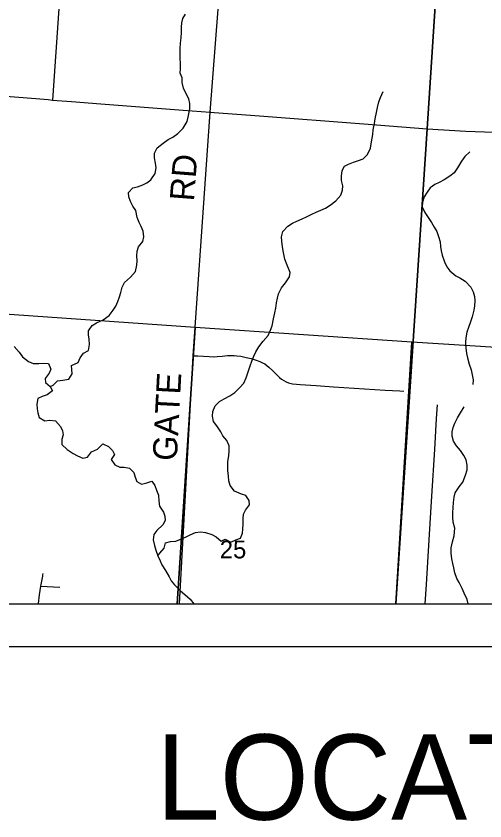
# Model space of a CAD drawing. Extents: x 0 to 34, y 0 to 22.
# Drawn here: x 4.098 to 5.197, y 13.591 to 15.479 of the extents above; entities that cross this region are included whole.
import ezdxf

# ---------------------------------------------------------------- set-up
doc = ezdxf.new("R2010")
doc.units = 0
for name, color, linetype in [('GM_X_Corporation', 7, 'Continuous'), ('GM_X_Minor_River', 7, 'Continuous'), ('GM_X_Section_Text', 7, 'Continuous'), ('GM_X_State_Route', 7, 'Continuous'), ('GM_X_Township_Road', 7, 'Continuous'), ('GM_X_Township_Road_Text', 7, 'Continuous'), ('GM_X_Unincorporated_Text', 7, 'Continuous'), ('SH_Cut_Line', 7, 'Continuous'), ('SH_Data', 7, 'Continuous'), ('SH_Text', 7, 'Continuous')]:
    doc.layers.add(name, color=color, linetype=linetype)

msp = doc.modelspace()

# ---------------------------------------------------------------- linework, layer by layer
at = {"layer": 'GM_X_Corporation'}
for points in [[(2.1, 15.9442), (2.1, 14.1), (4.9875, 14.1), (5.0611, 15.2147), (5.0952, 15.7318), (4.92, 15.7429), (4.5905, 15.7634), (4.2803, 15.787), (3.9945, 15.8088), (3.3132, 15.8609), (2.8362, 15.8952), (2.7799, 15.8989), (2.6921, 15.9056), (2.5827, 15.9132), (2.2903, 15.9292)], [(4.9875, 14.1), (8.9, 14.1), (8.9, 15.4827), (8.6741, 15.4976), (7.6503, 15.5653), (6.838, 15.6206), (6.624, 15.6351), (6.4, 15.6498), (6.1109, 15.6683), (5.9419, 15.6782), (5.0952, 15.7318), (5.0611, 15.2147)]]:
    msp.add_lwpolyline(points, close=True, dxfattribs=at)
at = {"layer": 'GM_X_Minor_River'}
for points in [[(4.1779, 14.6097), (4.1851, 14.6134), (4.1951, 14.6235), (4.2076, 14.6245), (4.2216, 14.6274), (4.229, 14.6399), (4.2287, 14.6501), (4.2277, 14.6596), (4.2433, 14.6663), (4.2483, 14.6773), (4.256, 14.6882), (4.2678, 14.6941), (4.2703, 14.7089), (4.2692, 14.7207), (4.2675, 14.731), (4.2676, 14.7408), (4.276, 14.7533), (4.2867, 14.7592), (4.3023, 14.7667), (4.3161, 14.7764), (4.3257, 14.7888), (4.3318, 14.7986), (4.3361, 14.8092), (4.34, 14.8205), (4.3432, 14.8308), (4.3463, 14.8433), (4.3521, 14.8538), (4.3663, 14.8666), (4.3774, 14.8798), (4.3806, 14.8945), (4.3815, 14.9051), (4.3812, 14.9165), (4.3813, 14.9275), (4.3852, 14.9377), (4.3952, 14.9498), (4.3972, 14.9608), (4.3955, 14.9745), (4.391, 14.9851), (4.3862, 14.9947), (4.3818, 15.0061), (4.3782, 15.0228), (4.3719, 15.0328), (4.3659, 15.0439), (4.3623, 15.0549), (4.3616, 15.0648), (4.3716, 15.0757), (4.3822, 15.0782), (4.3948, 15.0834), (4.4043, 15.0879), (4.4138, 15.095), (4.4242, 15.1093), (4.4263, 15.1229), (4.4245, 15.1336), (4.4227, 15.1461), (4.4225, 15.1571), (4.4287, 15.17), (4.4424, 15.1809), (4.4542, 15.1891), (4.4649, 15.1947), (4.4767, 15.2037), (4.4898, 15.2164), (4.499, 15.2315), (4.5022, 15.2459), (4.505, 15.2611), (4.5052, 15.274), (4.5026, 15.285), (4.4956, 15.298), (4.49, 15.3102), (4.4875, 15.3231), (4.4872, 15.3341), (4.4828, 15.3452), (4.4833, 15.3562), (4.4831, 15.3676), (4.4828, 15.3805), (4.4822, 15.3907), (4.4823, 15.4033), (4.4836, 15.4158), (4.4845, 15.4279), (4.4854, 15.4408), (4.4859, 15.4533), (4.4867, 15.4628), (4.4884, 15.4734), (4.4949, 15.4836)], [(4.8889, 15.1364), (4.9003, 15.14), (4.911, 15.1441), (4.9217, 15.1546), (4.9283, 15.1694), (4.9307, 15.1838), (4.9336, 15.2012), (4.9348, 15.2118), (4.9376, 15.2266), (4.9397, 15.2383), (4.9425, 15.2527), (4.9452, 15.2645), (4.948, 15.2777), (4.9523, 15.2879), (4.9581, 15.3019)], [(5.1616, 15.1609), (5.1493, 15.1492), (5.142, 15.1383), (5.1327, 15.1232), (5.1243, 15.1111), (5.1147, 15.1036), (5.1014, 15.095), (5.0892, 15.0887), (5.0789, 15.0839), (5.0686, 15.0764), (5.0609, 15.0659), (5.054, 15.0549), (5.0501, 15.0424), (5.0496, 15.0318), (5.0555, 15.0181), (5.0633, 15.0062), (5.0711, 14.9944), (5.0778, 14.9841), (5.0838, 14.9734), (5.0882, 14.9619), (5.0915, 14.949), (5.0929, 14.9384), (5.0943, 14.9281), (5.0961, 14.9178), (5.1016, 14.9022), (5.1071, 14.8911), (5.1142, 14.8816), (5.1281, 14.8693), (5.1379, 14.865), (5.1507, 14.8569), (5.1634, 14.8431), (5.169, 14.8324), (5.1719, 14.8214), (5.1729, 14.8111), (5.1721, 14.799), (5.1704, 14.7888), (5.1665, 14.7736), (5.1626, 14.7619), (5.1579, 14.7487), (5.154, 14.7373), (5.1519, 14.724), (5.1511, 14.7138), (5.1521, 14.7009), (5.1534, 14.6872), (5.156, 14.6769), (5.1596, 14.6621), (5.1644, 14.6491), (5.1669, 14.637), (5.1687, 14.6256), (5.1682, 14.6146)], [(4.4305, 14.2131), (4.4351, 14.2191), (4.4447, 14.2311), (4.4482, 14.2436), (4.46, 14.2465), (4.4721, 14.2468), (4.482, 14.2509), (4.4965, 14.2576), (4.506, 14.262), (4.5185, 14.2676), (4.5299, 14.2693), (4.5417, 14.2677), (4.5568, 14.263), (4.5669, 14.2572), (4.5782, 14.2472), (4.5881, 14.2517), (4.6009, 14.2447), (4.6127, 14.2503), (4.6241, 14.2539), (4.6284, 14.266), (4.6296, 14.2755), (4.6301, 14.2869), (4.6303, 14.3006), (4.6308, 14.3104), (4.6358, 14.3202), (4.6446, 14.3323), (4.6444, 14.3422), (4.6362, 14.354), (4.626, 14.3575), (4.6101, 14.3645), (4.5993, 14.3779), (4.5968, 14.389), (4.5954, 14.3996), (4.5944, 14.4129), (4.5941, 14.4235), (4.5942, 14.433), (4.5963, 14.4478), (4.5975, 14.4584), (4.5976, 14.4706), (4.5917, 14.4835), (4.5827, 14.4939), (4.5775, 14.5034), (4.5682, 14.5176), (4.5607, 14.5275), (4.5582, 14.5404), (4.5587, 14.5514), (4.5642, 14.5643), (4.5745, 14.5748), (4.5859, 14.5811), (4.5985, 14.5882), (4.6104, 14.5961), (4.6226, 14.6073), (4.6318, 14.6182), (4.6372, 14.63), (4.6423, 14.647), (4.6463, 14.6587), (4.6502, 14.6697), (4.6552, 14.6814), (4.6599, 14.6912), (4.6668, 14.7029), (4.6768, 14.7161), (4.6887, 14.73), (4.6945, 14.7425), (4.6977, 14.7527), (4.7012, 14.7686), (4.7044, 14.783), (4.7068, 14.7936), (4.7085, 14.8061), (4.7105, 14.8171), (4.7129, 14.8273), (4.7198, 14.8413), (4.7294, 14.8529), (4.739, 14.8673), (4.7399, 14.8775), (4.7333, 14.895), (4.7274, 14.9091), (4.7245, 14.924), (4.7224, 14.938), (4.7206, 14.951), (4.7196, 14.9612), (4.7228, 14.9733), (4.735, 14.9865), (4.7457, 14.9928), (4.756, 14.998), (4.7685, 15.0032), (4.7788, 15.0077), (4.7914, 15.014), (4.8013, 15.0188), (4.8123, 15.0237), (4.823, 15.0281), (4.8341, 15.0356), (4.8474, 15.0457), (4.8589, 15.0589), (4.8632, 15.0706), (4.8633, 15.0804), (4.8608, 15.093), (4.8602, 15.1036), (4.8618, 15.1169), (4.8672, 15.1267), (4.8768, 15.1319), (4.8889, 15.1364)], [(4.0933, 14.7035), (4.1053, 14.6905), (4.1131, 14.6798), (4.1274, 14.6686), (4.1376, 14.664), (4.1516, 14.6638), (4.1614, 14.6645), (4.1736, 14.664), (4.1791, 14.651), (4.1752, 14.6412), (4.1664, 14.6288), (4.167, 14.6193), (4.1779, 14.6097), (4.1835, 14.6001), (4.1705, 14.5908), (4.1591, 14.5863), (4.1492, 14.5819), (4.1468, 14.5686), (4.1474, 14.5576), (4.1488, 14.5481), (4.1517, 14.5371), (4.1657, 14.5297), (4.1767, 14.5311), (4.1903, 14.5295), (4.2019, 14.5164), (4.2071, 14.5061), (4.2081, 14.4966), (4.2054, 14.4864), (4.2052, 14.4743), (4.2176, 14.462), (4.2315, 14.4531), (4.2417, 14.4473), (4.2541, 14.4415), (4.2651, 14.444), (4.2747, 14.4565), (4.2888, 14.4631), (4.3014, 14.4752), (4.3143, 14.4693), (4.324, 14.4601), (4.3285, 14.4506), (4.3211, 14.4389), (4.3293, 14.4263), (4.3414, 14.4205), (4.3509, 14.4208), (4.3641, 14.4183), (4.3735, 14.4084), (4.3771, 14.3973), (4.3812, 14.387), (4.3917, 14.3805), (4.4043, 14.3838), (4.4161, 14.3882), (4.4231, 14.3775), (4.4268, 14.3668), (4.432, 14.3554), (4.4322, 14.3413), (4.434, 14.3292), (4.4433, 14.315), (4.4466, 14.3055), (4.4472, 14.2953), (4.4418, 14.2851), (4.4277, 14.2723), (4.4204, 14.2625), (4.4195, 14.25), (4.422, 14.2371), (4.4253, 14.2264), (4.4305, 14.2131), (4.4352, 14.2009), (4.4397, 14.1913), (4.4479, 14.1787), (4.4568, 14.1638), (4.4616, 14.1539), (4.4691, 14.1444), (4.4834, 14.1305), (4.4931, 14.1217), (4.5059, 14.111), (4.5144, 14.1)], [(5.1577, 14.1), (5.1548, 14.1107), (5.1481, 14.1255), (5.1433, 14.1358), (5.1359, 14.1503), (5.1311, 14.1599), (5.1263, 14.1732), (5.1234, 14.1846), (5.1212, 14.1945), (5.1194, 14.2059), (5.1177, 14.2188), (5.1178, 14.2314), (5.121, 14.2457), (5.1242, 14.2594), (5.1259, 14.2776), (5.1223, 14.292), (5.1213, 14.3038), (5.1214, 14.3144), (5.1222, 14.3251), (5.1231, 14.3376), (5.1244, 14.3505), (5.1272, 14.3607), (5.136, 14.3743), (5.1449, 14.3859), (5.1515, 14.4022), (5.1547, 14.4147), (5.1548, 14.4253), (5.1523, 14.4382), (5.1471, 14.4485), (5.1392, 14.4596), (5.1303, 14.4707), (5.1228, 14.4818), (5.1199, 14.4932), (5.12, 14.5039), (5.122, 14.5141), (5.1259, 14.5239), (5.1321, 14.5367), (5.1394, 14.5484), (5.1479, 14.5624)]]:
    msp.add_lwpolyline(points, dxfattribs=at)
at = {"layer": 'GM_X_State_Route'}
for p, q in [((4.4897, 15.2584), (4.5525, 15.2537)), ((4.5525, 15.2537), (4.5545, 15.2535)), ((4.5545, 15.2535), (4.5623, 15.2529))]:
    msp.add_line(p, q, dxfattribs=at)
for points in [[(4.0539, 15.2928), (4.1445, 15.2855), (4.1735, 15.283)], [(4.1735, 15.283), (4.1835, 15.2821), (4.2281, 15.2785), (4.2962, 15.273), (4.4897, 15.2584)], [(4.5623, 15.2529), (4.6682, 15.2448), (4.9129, 15.226), (5.0613, 15.2142), (5.1521, 15.2093), (5.3266, 15.2026), (5.5066, 15.1961), (5.6457, 15.1869), (5.7333, 15.1799), (5.8049, 15.1761), (5.9797, 15.1639)]]:
    msp.add_lwpolyline(points, dxfattribs=at)
at = {"layer": 'GM_X_Township_Road'}
msp.add_line((4.1563, 14.1419), (4.2003, 14.139), dxfattribs=at)
for points in [[(4.5525, 15.2537), (4.5897, 15.7276), (4.5907, 15.7628)], [(4.1985, 15.4966), (4.1835, 15.2821)], [(4.4806, 14.1), (4.5132, 14.6819), (4.5525, 15.2537)], [(4.5132, 14.6819), (4.5236, 14.6817), (4.5501, 14.68), (4.5595, 14.6798), (4.5688, 14.6801), (4.5812, 14.6812), (4.5936, 14.6826), (4.6029, 14.683), (4.6091, 14.6828), (4.6153, 14.6823), (4.6246, 14.6808), (4.6368, 14.6783), (4.6488, 14.6753), (4.6607, 14.6717), (4.6695, 14.6684), (4.6751, 14.6658), (4.6806, 14.6628), (4.6857, 14.6593), (4.6905, 14.6553), (4.6996, 14.6468), (4.7151, 14.6315), (4.7199, 14.6275), (4.7251, 14.6241), (4.7306, 14.6212), (4.7364, 14.6188), (4.7393, 14.6178), (4.7454, 14.6165), (4.7547, 14.6153), (4.7639, 14.6144), (4.8013, 14.6123), (4.8417, 14.6094), (4.9628, 14.6015), (4.997, 14.5995), (5.0063, 14.5987)], [(5.0566, 14.1), (5.0596, 14.1452), (5.0658, 14.2506), (5.0724, 14.3529), (5.0789, 14.4624), (5.0832, 14.5347), (5.0855, 14.5672)], [(4.1503, 14.1), (4.1504, 14.1012), (4.1531, 14.1216), (4.1563, 14.1419), (4.1583, 14.1535), (4.1605, 14.165), (4.161, 14.168), (4.1613, 14.171)]]:
    msp.add_lwpolyline(points, dxfattribs=at)
at = {"layer": 'GM_X_Unincorporated_Text'}
for points in [[(3.9696, 14.1), (4.4753, 14.1), (4.5173, 14.7485), (4.0145, 14.7837)], [(4.4753, 14.1), (4.9875, 14.1), (5.0255, 14.7138), (4.5173, 14.7485)], [(4.9875, 14.1), (5.5277, 14.1), (5.5568, 14.6807), (5.0255, 14.7138)]]:
    msp.add_lwpolyline(points, close=True, dxfattribs=at)
at = {"layer": 'SH_Cut_Line'}
msp.add_lwpolyline([(2.1, 15.9442), (2.1, 14.1), (8.9, 14.1), (8.9, 15.4827), (8.6741, 15.4976), (7.6503, 15.5653), (6.838, 15.6206), (6.624, 15.6351), (6.4, 15.6498), (6.1109, 15.6683), (5.9419, 15.6782), (5.0952, 15.7318), (4.92, 15.7429), (4.5905, 15.7634), (4.2803, 15.787), (3.9945, 15.8088), (3.3132, 15.8609), (2.8362, 15.8952), (2.7799, 15.8989), (2.6921, 15.9056), (2.5827, 15.9132), (2.2903, 15.9292)], close=True, dxfattribs=at)
at = {"layer": 'SH_Data'}
msp.add_line((2, 14), (9, 14), dxfattribs=at)

# ---------------------------------------------------------------- texts
at = {"layer": 'GM_X_Section_Text'}
msp.add_text('25', height=0.04186, rotation=0, dxfattribs=at).set_placement((4.5752, 14.2068))
at = {"layer": 'GM_X_Township_Road_Text'}
for s, rotation, p in [('RD', 85.564, (4.5146, 15.0435)), ('GATE', 87.0397, (4.4746, 14.4346))]:
    msp.add_text(s, height=0.05682, rotation=rotation, dxfattribs=at).set_placement(p)
at = {"layer": 'SH_Text'}
msp.add_text('LOCATION MAP', height=0.2, dxfattribs=at).set_placement((4.4269, 13.5938))

doc.saveas('drawing.dxf')
